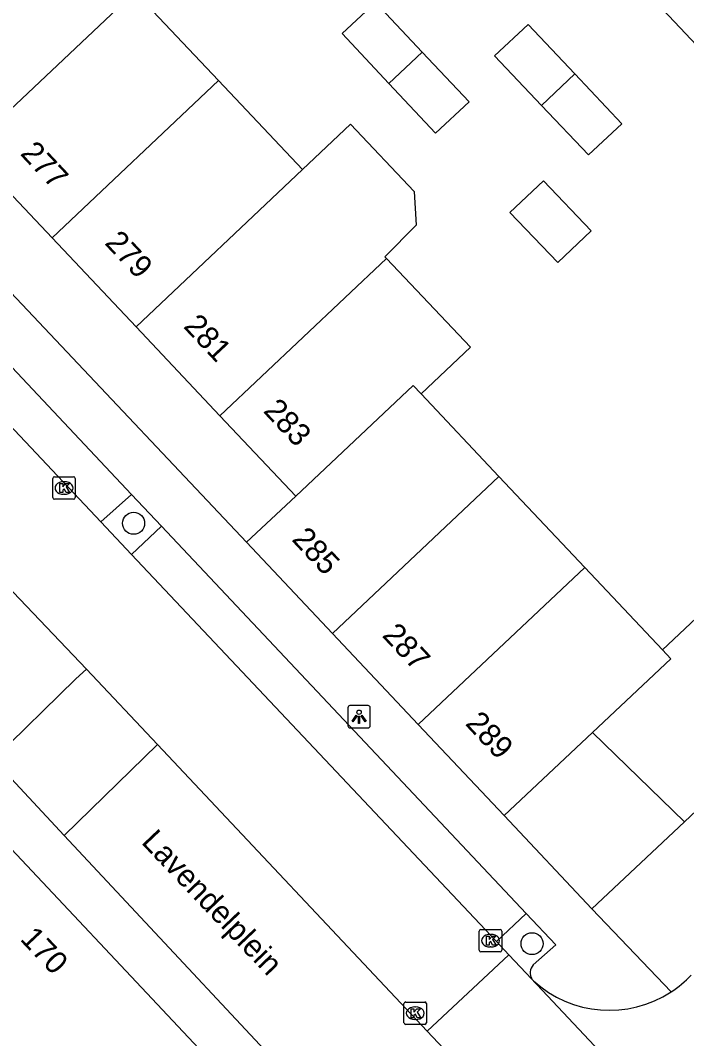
# Model space of a CAD drawing. Extents: x 162542 to 163144, y 380786 to 381511.
# Drawn here: x 162894.26 to 162923.93, y 381374.74 to 381420.09 of the extents above; entities that cross this region are included whole.
import ezdxf

# ---------------------------------------------------------------- set-up
doc = ezdxf.new("R2010")
doc.units = 0
for name, color, linetype in [('IMGEO_Boom', 7, 'Continuous'), ('IMGEO_Groenvoorziening', 7, 'Continuous'), ('IMGEO_Kolk', 7, 'Continuous'), ('IMGEO_Lichtpunt', 7, 'Continuous'), ('IMGEO_Openbare_ruimte_label', 7, 'Continuous'), ('IMGEO_Pand', 7, 'Continuous'), ('IMGEO_Pand_nummerreeks', 7, 'Continuous'), ('IMGEO_Parkeervlak_open', 7, 'Continuous'), ('IMGEO_Rijbaan_lokaal_open', 7, 'Continuous'), ('IMGEO_Voetpad_open', 7, 'Continuous')]:
    doc.layers.add(name, color=color, linetype=linetype)

msp = doc.modelspace()

# ---------------------------------------------------------------- linework, layer by layer
at = {"layer": 'IMGEO_Boom'}
for centre in [(162899.298, 381397.696), (162917.043, 381378.972)]:
    msp.add_circle(centre, 0.489, dxfattribs=at)
at = {"layer": 'IMGEO_Groenvoorziening'}
msp.add_lwpolyline([(162896.201, 381383.789), (162900.36, 381387.84)], dxfattribs=at)
at = {"layer": 'IMGEO_Kolk'}
for p, q in [((162895.698, 381398.84), (162895.698, 381399.692)), ((162895.773, 381399.766), (162896.625, 381399.766)), ((162896.186, 381399.546), (162896.211, 381399.546)), ((162896.699, 381399.692), (162896.699, 381398.84)), ((162896.625, 381398.766), (162895.773, 381398.766)), ((162896.209, 381398.986), (162896.184, 381398.986)), ((162914.769, 381379.606), (162915.621, 381379.606)), ((162914.694, 381378.68), (162914.694, 381379.532)), ((162915.182, 381379.386), (162915.207, 381379.386)), ((162915.695, 381379.532), (162915.695, 381378.68)), ((162915.205, 381378.826), (162915.18, 381378.826)), ((162915.621, 381378.606), (162914.769, 381378.606)), ((162911.34, 381375.448), (162911.34, 381376.3)), ((162911.415, 381376.374), (162912.267, 381376.374)), ((162911.828, 381376.154), (162911.853, 381376.154)), ((162912.341, 381376.3), (162912.341, 381375.448)), ((162911.851, 381375.594), (162911.826, 381375.594)), ((162912.267, 381375.374), (162911.415, 381375.374))]:
    msp.add_line(p, q, dxfattribs=at)
for points in [[(162895.698, 381398.84), (162895.698, 381399.692)], [(162895.773, 381399.766), (162896.625, 381399.766)], [(162896.699, 381399.692), (162896.699, 381398.84)], [(162896.019, 381399.466), (162896.142, 381399.466), (162896.142, 381399.315), (162896.272, 381399.466), (162896.436, 381399.466), (162896.29, 381399.315), (162896.443, 381399.066), (162896.291, 381399.066), (162896.206, 381399.23), (162896.142, 381399.163), (162896.142, 381399.066), (162896.019, 381399.066), (162896.019, 381399.466)], [(162896.625, 381398.766), (162895.773, 381398.766)], [(162914.769, 381379.606), (162915.621, 381379.606)], [(162914.694, 381378.68), (162914.694, 381379.532)], [(162915.015, 381379.306), (162915.138, 381379.306), (162915.138, 381379.155), (162915.268, 381379.306), (162915.432, 381379.306), (162915.286, 381379.155), (162915.439, 381378.906), (162915.287, 381378.906), (162915.202, 381379.07), (162915.138, 381379.003), (162915.138, 381378.906), (162915.015, 381378.906), (162915.015, 381379.306)], [(162915.695, 381379.532), (162915.695, 381378.68)], [(162915.621, 381378.606), (162914.769, 381378.606)], [(162911.34, 381375.448), (162911.34, 381376.3)], [(162911.415, 381376.374), (162912.267, 381376.374)], [(162911.661, 381376.074), (162911.784, 381376.074), (162911.784, 381375.923), (162911.914, 381376.074), (162912.078, 381376.074), (162911.932, 381375.923), (162912.085, 381375.674), (162911.933, 381375.674), (162911.848, 381375.838), (162911.784, 381375.771), (162911.784, 381375.674), (162911.661, 381375.674), (162911.661, 381376.074)], [(162912.341, 381376.3), (162912.341, 381375.448)], [(162912.267, 381375.374), (162911.415, 381375.374)]]:
    msp.add_lwpolyline(points, dxfattribs=at)
for centre, start, end in [((162895.775, 381399.69), 91.552, 178.448), ((162895.775, 381399.69), 91.552, 178.448), ((162896.623, 381399.69), 1.552, 88.448), ((162896.623, 381399.69), 1.552, 88.448), ((162895.775, 381398.842), 181.552, 268.448), ((162895.775, 381398.842), 181.552, 268.448), ((162896.623, 381398.842), 271.552, 358.448), ((162896.623, 381398.842), 271.552, 358.448), ((162914.771, 381379.53), 91.552, 178.448), ((162914.771, 381379.53), 91.552, 178.448), ((162915.619, 381379.53), 1.552, 88.448), ((162915.619, 381379.53), 1.552, 88.448), ((162914.771, 381378.682), 181.552, 268.448), ((162914.771, 381378.682), 181.552, 268.448), ((162915.619, 381378.682), 271.552, 358.448), ((162915.619, 381378.682), 271.552, 358.448), ((162911.417, 381376.298), 91.552, 178.448), ((162911.417, 381376.298), 91.552, 178.448), ((162912.265, 381376.298), 1.552, 88.448), ((162912.265, 381376.298), 1.552, 88.448), ((162911.417, 381375.45), 181.552, 268.448), ((162911.417, 381375.45), 181.552, 268.448), ((162912.265, 381375.45), 271.552, 358.448), ((162912.265, 381375.45), 271.552, 358.448)]:
    msp.add_arc(centre, 0.0765, start, end, dxfattribs=at)
for centre, major_axis, ratio, start_param, end_param in [((162896.185, 381399.266), (-0.387, 0.002), 0.722429, 4.712389, 7.853982), ((162896.21, 381399.266), (-0.39, 0.002), 0.717154, 1.570796, 4.712389), ((162915.181, 381379.106), (-0.387, 0.002), 0.722429, 4.712389, 7.853982), ((162915.206, 381379.106), (-0.39, 0.002), 0.717154, 1.570796, 4.712389), ((162911.827, 381375.874), (-0.387, 0.002), 0.722429, 4.712389, 7.853982), ((162911.852, 381375.874), (-0.39, 0.002), 0.717154, 1.570796, 4.712389)]:
    msp.add_ellipse(centre, major_axis=major_axis, ratio=ratio, start_param=start_param, end_param=end_param, dxfattribs=at)
at = {"layer": 'IMGEO_Lichtpunt'}
for p, q in [((162909.742, 381389.576), (162908.934, 381389.576)), ((162909.742, 381389.576), (162908.934, 381389.576)), ((162908.84, 381389.481), (162908.84, 381388.674)), ((162908.84, 381389.481), (162908.84, 381388.674)), ((162909.836, 381388.674), (162909.836, 381389.481)), ((162909.836, 381388.674), (162909.836, 381389.481)), ((162908.934, 381388.58), (162909.742, 381388.58)), ((162908.934, 381388.58), (162909.742, 381388.58))]:
    msp.add_line(p, q, dxfattribs=at)
for points in [[(162909.214, 381389.145), (162909.253, 381389.117), (162909.065, 381388.855), (162909.027, 381388.882), (162909.214, 381389.145)], [(162909.316, 381389.097), (162909.363, 381389.097), (162909.363, 381388.775), (162909.316, 381388.775), (162909.316, 381389.097)], [(162909.426, 381389.117), (162909.464, 381389.144), (162909.651, 381388.882), (162909.612, 381388.854), (162909.426, 381389.117)]]:
    msp.add_lwpolyline(points, dxfattribs=at)
msp.add_circle((162909.339, 381389.279), 0.0994, dxfattribs=at)
for centre, start, end in [((162908.934, 381389.481), 90, 180), ((162908.934, 381389.481), 90, 180), ((162909.742, 381389.481), 0, 90), ((162909.742, 381389.481), 0, 90), ((162908.934, 381388.674), 180, 270), ((162908.934, 381388.674), 180, 270), ((162909.742, 381388.674), 270, 0), ((162909.742, 381388.674), 270, 360)]:
    msp.add_arc(centre, 0.0946, start, end, dxfattribs=at)
at = {"layer": 'IMGEO_Pand'}
for points in [[(162930.802, 381421.057), (162928.61, 381418.989), (162926.365, 381416.871), (162922.63, 381420.825), (162924.875, 381422.945)], [(162891.93, 381414.362), (162899.346, 381421.365)], [(162899.346, 381421.365), (162903.084, 381417.407)], [(162910.668, 381417.282), (162908.58, 381419.503), (162910.064, 381420.895), (162912.152, 381418.681)], [(162917.468, 381416.306), (162915.375, 381418.515), (162916.869, 381419.915), (162918.948, 381417.709)], [(162912.152, 381418.681), (162914.239, 381416.466), (162912.749, 381415.07), (162910.668, 381417.282)], [(162912.152, 381418.681), (162910.668, 381417.282)], [(162918.948, 381417.709), (162921.047, 381415.482), (162919.56, 381414.097), (162917.468, 381416.306)], [(162918.948, 381417.709), (162917.468, 381416.306)], [(162895.668, 381410.403), (162903.084, 381417.407)], [(162903.084, 381417.407), (162906.823, 381413.449)], [(162906.823, 381413.449), (162908.963, 381415.47), (162911.792, 381412.475), (162911.883, 381410.971), (162910.494, 381409.562), (162910.561, 381409.491)], [(162895.668, 381410.403), (162891.93, 381414.362)], [(162906.823, 381413.449), (162899.406, 381406.444)], [(162917.555, 381412.948), (162919.672, 381410.713), (162918.192, 381409.308), (162916.061, 381411.541), (162917.555, 381412.948)], [(162899.406, 381406.444), (162895.668, 381410.403)], [(162903.143, 381402.486), (162910.561, 381409.491)], [(162910.561, 381409.491), (162914.299, 381405.533), (162912.099, 381403.46)], [(162899.406, 381406.444), (162903.143, 381402.486)], [(162906.52, 381398.909), (162911.747, 381403.833), (162912.099, 381403.46)], [(162912.099, 381403.46), (162915.569, 381399.779)], [(162906.52, 381398.909), (162903.143, 381402.486)], [(162915.569, 381399.779), (162908.153, 381392.793)], [(162915.569, 381399.779), (162919.391, 381395.725)], [(162904.333, 381396.849), (162906.52, 381398.909)], [(162908.153, 381392.793), (162904.333, 381396.849)], [(162922.852, 381392.054), (162928.121, 381397.021), (162932.398, 381392.485)], [(162911.974, 381388.738), (162919.391, 381395.725)], [(162919.391, 381395.725), (162922.852, 381392.054)], [(162911.974, 381388.738), (162908.153, 381392.793)], [(162932.398, 381392.485), (162923.826, 381384.403)], [(162919.737, 381388.38), (162923.229, 381391.655), (162922.852, 381392.054)], [(162915.794, 381384.682), (162911.974, 381388.738)], [(162919.737, 381388.38), (162915.794, 381384.682)], [(162923.826, 381384.403), (162919.737, 381388.38)], [(162891.278, 381385.908), (162903.602, 381372.816)]]:
    msp.add_lwpolyline(points, dxfattribs=at)
at = {"layer": 'IMGEO_Parkeervlak_open'}
for points in [[(162899.205, 381398.982), (162897.835, 381397.758)], [(162899.21, 381396.299), (162900.543, 381397.562)], [(162915.46, 381379.065), (162916.781, 381380.313)]]:
    msp.add_lwpolyline(points, dxfattribs=at)
at = {"layer": 'IMGEO_Rijbaan_lokaal_open'}
for points in [[(162897.835, 381397.758), (162885.817, 381410.504)], [(162899.21, 381396.299), (162897.835, 381397.758)], [(162915.46, 381379.065), (162899.21, 381396.299)], [(162897.205, 381391.195), (162893.031, 381395.568)], [(162900.36, 381387.84), (162897.205, 381391.195)], [(162912.37, 381375.072), (162900.36, 381387.84)], [(162916.012, 381378.48), (162915.46, 381379.065)], [(162916.012, 381378.48), (162912.37, 381375.072)], [(162917.032, 381377.398), (162916.012, 381378.48)], [(162927.021, 381366.758), (162917.032, 381377.398)], [(162917.032, 381377.398), (162917.107, 381377.321)], [(162913.114, 381374.284), (162912.37, 381375.072)]]:
    msp.add_lwpolyline(points, dxfattribs=at)
for centre, radius, start, end in [((162920.491, 381381.009), 5.005, 227.4658, 303.3039), ((162920.443, 381381.059), 5.073, 303.4413, 316.5129)]:
    msp.add_arc(centre, radius, start, end, dxfattribs=at)
at = {"layer": 'IMGEO_Voetpad_open'}
for points in [[(162904.333, 381396.849), (162867.324, 381436.054), (162869.505, 381438.114)], [(162887.154, 381411.783), (162899.205, 381398.982)], [(162899.205, 381398.982), (162900.543, 381397.562)], [(162900.543, 381397.562), (162916.781, 381380.313)], [(162893.039, 381387.172), (162896.723, 381390.77), (162897.205, 381391.195)], [(162893.039, 381387.172), (162896.201, 381383.789)], [(162919.711, 381380.523), (162915.794, 381384.682)], [(162923.826, 381384.403), (162919.711, 381380.523)], [(162896.201, 381383.789), (162908.744, 381370.37)], [(162923.239, 381376.826), (162919.711, 381380.523)], [(162916.781, 381380.313), (162918.098, 381378.914), (162917.098, 381378.024)]]:
    msp.add_lwpolyline(points, dxfattribs=at)
msp.add_arc((162917.495, 381377.666), 0.534, 137.9036, 210.0593, dxfattribs=at)

# ---------------------------------------------------------------- texts
at = {"layer": 'IMGEO_Openbare_ruimte_label'}
msp.add_text('Lavendelplein', height=1, rotation=313.5416, dxfattribs=at).set_placement((162899.605, 381383.466))
at = {"layer": 'IMGEO_Pand_nummerreeks'}
for s, rotation, p in [('277', 313.155, (162894.214, 381414.134)), ('279', 313.155, (162897.975, 381410.151)), ('281', 313.155, (162901.483, 381406.436)), ('283', 313.155, (162905.038, 381402.671)), ('285', 313.0862, (162906.306, 381396.948)), ('287', 313.0977, (162910.332, 381392.675)), ('289', 313.0862, (162914.035, 381388.744)), ('170', 313.2696, (162894.205, 381379.151))]:
    msp.add_text(s, height=1, rotation=rotation, dxfattribs=at).set_placement(p)

doc.saveas('drawing.dxf')
